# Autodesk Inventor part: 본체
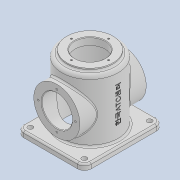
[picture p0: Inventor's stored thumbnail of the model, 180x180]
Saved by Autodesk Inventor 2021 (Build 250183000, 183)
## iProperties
Created: 2021-02
Part Number: 본체
Material: 알루미늄 6061
Document SubType Name: Modeling
Designer: sjtjd
Density: 2.7 g/cm^3
Appearance: 기본값
Mass: 1235.53 g
Surface Area: 1067.61 cm^2
Volume: 457.603 cm^3
Author: sjtjd
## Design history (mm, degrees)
sketch "스케치1"
  geometry: L1 (70, -60)-(-70, -60); L2 (-70, -60)-(-70, 60); L3 (-70, 60)-(70, 60); L4 (70, 60)-(70, -60); L5 (70, -60)-(-70, 60); L6 (-70, -60)-(70, 60); 1 further point
  constraints: 12 end point, 2 midpoint, 2 parallel, 1 horizontal, 1 perpendicular
  dimensions: "d0" = 140 distance of L2.end L3.end; "d1" = 120 distance of L1.end L2.end
extrude "돌출1" new body sketch "스케치1" distance "d2" = 10; taper "d3" = 0 deg
sketch "스케치2"
  geometry: C1 r 50 at (0, 0); 1 further point
  constraints: 1 centre point, 1 coincident
  dimensions: "d4" = 100 diameter of C1
extrude "돌출2" join sketch "스케치2" distance "d5" = 110; taper "d6" = 0 deg
sketch "스케치3"
  geometry: C1 r 42 at (0, 0); 1 further point
  constraints: 1 centre point, 1 coincident
  dimensions: "d7" = 84 diameter of C1
extrude "돌출3" cut sketch "스케치3" distance "d8" = 112; taper "d9" = 0 deg
sketch "스케치4"
  geometry: C1 r 27 at (0, 0); 1 further point
  constraints: 1 centre point, 1 coincident
  dimensions: "d10" = 54 diameter of C1
extrude "돌출4" cut sketch "스케치4" extent not by distance; stored distance "d11" = 0; taper "d12" = 0 deg
node "작업 평면1"
sketch "스케치5"
  geometry: L1 (0, 60)-(0, -60) reference; C1 r 41 at (59.98, 0); 2 further points
  constraints: 1 centre point, 1 horizontal alignment, 1 midpoint
  dimensions: "d14" = 82 diameter of C1; "d15" = 59.98 distance from line of L1 C1.centre
extrude "돌출5" join sketch "스케치5" stored distance "d16" = 118; taper "d17" = 0 deg
sketch "스케치6"
  geometry: C1 r 41 at (0, 0) reference; C2 r 27 at (0, 0); 1 further point
  constraints: 1 centre point, 1 coincident
  dimensions: "d18" = 54 diameter of C2
extrude "돌출6" cut sketch "스케치6" extent not by distance; stored distance "d19" = 0; taper "d20" = 0 deg
sketch "스케치7"
  geometry: C1 r 41 at (0, 0) reference; A1 r 33 centre (0, 0) between (0, 33) and (33, 0); 3 further points
  constraints: 4 point on circle, 1 centre point, 1 coincident, 1 horizontal alignment, 1 vertical alignment
  dimensions: "d21" = 66 diameter of A1; "d22" = 66 distance of point (0, -33) A1.start; "d23" = 66 distance of point (-33, 0) A1.end
hole "구멍1" sketch "스케치7" at (0, 33), (33, 0), (0, -33), (-33, 0) diameter "d24" = 3.242; stored, may be unused: countersink angle "d28" = 82 deg, drill point angle "d30" = 118 deg; dims "d25" = 8, "d26" = 3.023, "d27" = 2, "d29" = 10
sketch "스케치8"
  geometry: C1 r 41 at (0, 0); C2 r 27 at (0, 0) reference; 1 further point
  constraints: 1 centre point, 1 coincident
  dimensions: "d31" = 82 diameter of C1
extrude "돌출7" join sketch "스케치8" distance "d32" = 5; taper "d33" = 0 deg
fillet "모깎기1" dims "d34" = 12
sketch "스케치9"
  geometry: A1 r 12 centre (-58, 48) between (-58, 60) and (-70, 48) reference; A2 r 12 centre (-58, -48) between (-70, -48) and (-58, -60) reference; A3 r 12 centre (58, -48) between (58, -60) and (70, -48) reference; A4 r 12 centre (58, 48) between (70, 48) and (58, 60) reference; 5 further points
  constraints: 4 coincident
hole "구멍2" sketch "스케치9" at (-58, 48), (58, 48), (58, -48), (-58, -48) diameter "d35" = 9; stored, may be unused: countersink angle "d39" = 82 deg, drill point angle "d41" = 118 deg; dims "d36" = 8, "d37" = 3.023, "d38" = 2, "d40" = 10
sketch "스케치10" dims "d42" = 66
  geometry: 3 further points
  constraints: 2 vertical alignment, 1 coincident, 2 other
hole "구멍3" sketch "스케치10" diameter "d43" = 3.242; stored, may be unused: countersink angle "d47" = 82 deg, drill point angle "d49" = 118 deg; dims "d44" = 8, "d45" = 3.023, "d46" = 2, "d48" = 10
fillet "모깎기2" dims "d53" = 6
fillet "모깎기3" dims "d54" = 3
fillet "모깎기4" dims "d55" = 3
fillet "모깎기5" dims "d56" = 3
fillet "모깎기6" dims "d57" = 3
chamfer "모따기1" distance "d58" = 1; stored, may be unused: second distance "d59" = 2, angle "d60" = 45 deg
node "작업 평면2"
sketch "스케치11"
  geometry: L1 (-58, 0)-(58, 0) reference; 2 further points
  constraints: 1 vertical alignment, 1 other
  dimensions: "d62" = 66 distance from line of L1 point (0, 66)
feature "엠보싱1" sketch "스케치11" dims "d0" = 140, "d1" = 120, "d63" = 0.5, "d64" = 0
node "솔리드1"
mirror "미러1"
mirror "미러2"
pattern_circular "원형 패턴1" dims angle "d51" = 360 deg
feature "A9D066F2-1C7D-4E18-AEED-F7BC21143FA4" dims "d35" = 9, "d36" = 8, "d37" = 3.023, "d38" = 2, "d39" = 82 deg, "d40" = 10, "d41" = 118 deg
other parameters: "d13" = 59, "d61" = -69
